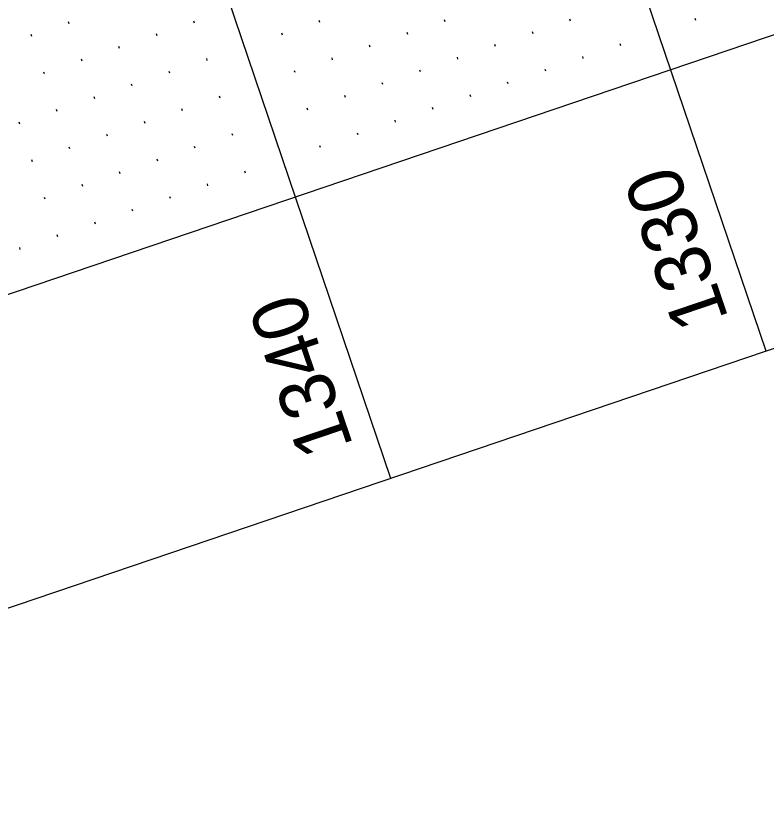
# Model space of a CAD drawing. Extents: x 2150800 to 2152547, y 141860 to 143950.
# Drawn here: x 2151935.4 to 2152030.1, y 142214 to 142312.9 of the extents above; entities that cross this region are included whole.
import ezdxf

# ---------------------------------------------------------------- set-up
doc = ezdxf.new("R2010")
doc.units = 0
for name, color, linetype in [('SHT_Plan_Profile_Sheet_Elev_Txt', 7, 'Continuous'), ('SHT_Profile_Grid_Major', 7, 'Continuous'), ('SHT_Profile_Grid_Minor', 7, 'Continuous'), ('SHT_Sheet_Border', 7, 'Continuous')]:
    doc.layers.add(name, color=color, linetype=linetype)

msp = doc.modelspace()

# ---------------------------------------------------------------- linework, layer by layer
at = {"layer": 'SHT_Profile_Grid_Major'}
for p, q in [((2152030.062, 142270.543), (2151524.072, 143762.052)), ((2151982.713, 142254.48), (2151476.723, 143745.989))]:
    msp.add_line(p, q, dxfattribs=at)
at = {"layer": 'SHT_Profile_Grid_Minor'}
for p, q in [((2151957.939, 142311.942), (2151957.858, 142312.179)), ((2151973.75, 142312.026), (2151973.67, 142312.263)), ((2151989.561, 142312.11), (2151989.481, 142312.347)), ((2152005.372, 142312.194), (2152005.292, 142312.431)), ((2152021.184, 142312.278), (2152021.103, 142312.515)), ((2151942.128, 142311.858), (2151942.047, 142312.095)), ((2151937.393, 142310.252), (2151937.312, 142310.489)), ((2151953.204, 142310.336), (2151953.124, 142310.573)), ((2151969.015, 142310.42), (2151968.935, 142310.657)), ((2151984.826, 142310.504), (2151984.746, 142310.741)), ((2152000.637, 142310.588), (2152000.557, 142310.825)), ((2151995.902, 142308.982), (2151995.822, 142309.219)), ((2152011.714, 142309.066), (2152011.633, 142309.303)), ((2151948.469, 142308.73), (2151948.389, 142308.966)), ((2151980.091, 142308.898), (2151980.011, 142309.135)), ((2151943.734, 142307.123), (2151943.654, 142307.36)), ((2151959.545, 142307.207), (2151959.465, 142307.444)), ((2151975.356, 142307.291), (2151975.276, 142307.528)), ((2151991.167, 142307.375), (2151991.087, 142307.612)), ((2152006.979, 142307.459), (2152006.898, 142307.696)), ((2151938.999, 142305.517), (2151938.919, 142305.754)), ((2151954.81, 142305.601), (2151954.73, 142305.838)), ((2151970.621, 142305.685), (2151970.541, 142305.922)), ((2151986.433, 142305.769), (2151986.352, 142306.006)), ((2152002.244, 142305.853), (2152002.163, 142306.09)), ((2151981.698, 142304.163), (2151981.617, 142304.4)), ((2151997.509, 142304.247), (2151997.428, 142304.484)), ((2151950.075, 142303.995), (2151949.995, 142304.232)), ((2151945.34, 142302.388), (2151945.26, 142302.625)), ((2151961.151, 142302.472), (2151961.071, 142302.709)), ((2151976.963, 142302.557), (2151976.882, 142302.793)), ((2151992.774, 142302.641), (2151992.693, 142302.877)), ((2151940.605, 142300.782), (2151940.525, 142301.019)), ((2151956.416, 142300.866), (2151956.336, 142301.103)), ((2151972.228, 142300.95), (2151972.147, 142301.187)), ((2151988.039, 142301.034), (2151987.959, 142301.271)), ((2151935.87, 142299.176), (2151935.79, 142299.413)), ((2151951.682, 142299.26), (2151951.601, 142299.497)), ((2151983.304, 142299.428), (2151983.224, 142299.665)), ((2151946.947, 142297.654), (2151946.866, 142297.89)), ((2151962.758, 142297.738), (2151962.677, 142297.974)), ((2151978.569, 142297.822), (2151978.489, 142298.058)), ((2151958.023, 142296.131), (2151957.942, 142296.368)), ((2151973.834, 142296.215), (2151973.754, 142296.452)), ((2151942.212, 142296.047), (2151942.131, 142296.284)), ((2151937.477, 142294.441), (2151937.396, 142294.678)), ((2151953.288, 142294.525), (2151953.208, 142294.762)), ((2151948.553, 142292.919), (2151948.473, 142293.155)), ((2151964.364, 142293.003), (2151964.284, 142293.239)), ((2151943.818, 142291.312), (2151943.738, 142291.549)), ((2151959.629, 142291.396), (2151959.549, 142291.633)), ((2151939.083, 142289.706), (2151939.003, 142289.943)), ((2151954.894, 142289.79), (2151954.814, 142290.027)), ((2151950.159, 142288.184), (2151950.079, 142288.42)), ((2151945.424, 142286.577), (2151945.344, 142286.814)), ((2151940.689, 142284.971), (2151940.609, 142285.208)), ((2151935.954, 142283.365), (2151935.874, 142283.601))]:
    msp.add_line(p, q, dxfattribs=at)
at = {"layer": 'SHT_Sheet_Border'}
msp.add_line((2152349.461, 142418.498), (2151875.966, 142257.866), dxfattribs=at)
msp.add_lwpolyline([(2151383.741, 142051.281), (2150877.752, 143542.79), (2151872.092, 143880.117), (2152378.081, 142388.607)], close=True, dxfattribs=at)

# ---------------------------------------------------------------- texts
at = {"layer": 'SHT_Plan_Profile_Sheet_Elev_Txt'}
for s, p in [('1330', (2152025.34, 142274.638)), ('1340', (2151977.99, 142258.575))]:
    msp.add_text(s, height=7, rotation=108.73933, dxfattribs=at).set_placement(p)

doc.saveas('drawing.dxf')
